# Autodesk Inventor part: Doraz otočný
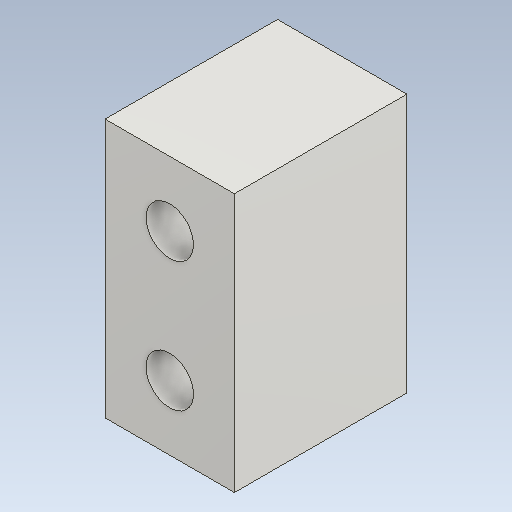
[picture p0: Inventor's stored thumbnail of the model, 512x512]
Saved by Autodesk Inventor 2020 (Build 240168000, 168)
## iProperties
Created: 2025-03
Part Number: Doraz otočný
Material: Ocel
Document SubType Name: Modeling
Designer: doma
Density: 7.85 g/cm^3
Appearance: Ocel
Mass: 60.061 g
Surface Area: 34.0607 cm^2
Volume: 7.65108 cm^3
Author: doma
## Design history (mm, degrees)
sketch "Náčrt1"
  geometry: L1 (-7.5, -15)-(7.5, -15); L2 (7.5, -15)-(7.5, 15); L3 (7.5, 15)-(-7.5, 15); L4 (-7.5, 15)-(-7.5, -15); L5 (-7.5, -15)-(7.5, 15); L6 (7.5, -15)-(-7.5, 15); L7 (0, 15)-(0, 7.5); L8 (0, 7.5)-(0, 0); L9 (0, -7.5)-(0, -15); L10 (0, 0)-(0, -7.5)
  constraints: 20 end point, 4 midpoint, 3 equal length, 2 collinear, 2 vertical, 1 horizontal, 1 perpendicular
  dimensions: "d0" = 15 distance of L3.end L2.end; "d1" = 30 distance of L2.end L1.end
extrude "Vysunutí1" new body sketch "Náčrt1" distance "d2" = 20; taper "d3" = 0 deg
hole "Díra1" sketch "Náčrt1" diameter "d4" = 5.5; stored, may be unused: countersink angle "d8" = 90 deg, drill point angle "d10" = 118 deg; dims "d5" = 25, "d6" = 9, "d7" = 5, "d9" = 32
node "Těleso1"
